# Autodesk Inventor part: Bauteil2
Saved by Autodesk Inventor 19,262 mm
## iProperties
Created: 2011-07
Part Number: Bauteil2
Material: S355J2+N(Cu<0,4%)
Document SubType Name: Blech
Density: 7.85 g/cm^3
Flat Pattern Width: 1.92619 cm
Flat Pattern Length: 1.98386 cm
Flat Pattern Area: 3.8213 cm^2
Sheet Metal Rule: Standard
Sheet Metal Width: 19,839 mm
Sheet Metal Length: 382,130 mm^2
MatBom2.0.1.: PS!Inventor!PV!14.0  SP: 3!AVMa!2!AVMi!0!AVBu!0
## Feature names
1. Extrusion1
2. Extrusion2
3. Rundung3 [Fillet]
4. Extrusion3
5. Extrusion4
6. Extrusion5
